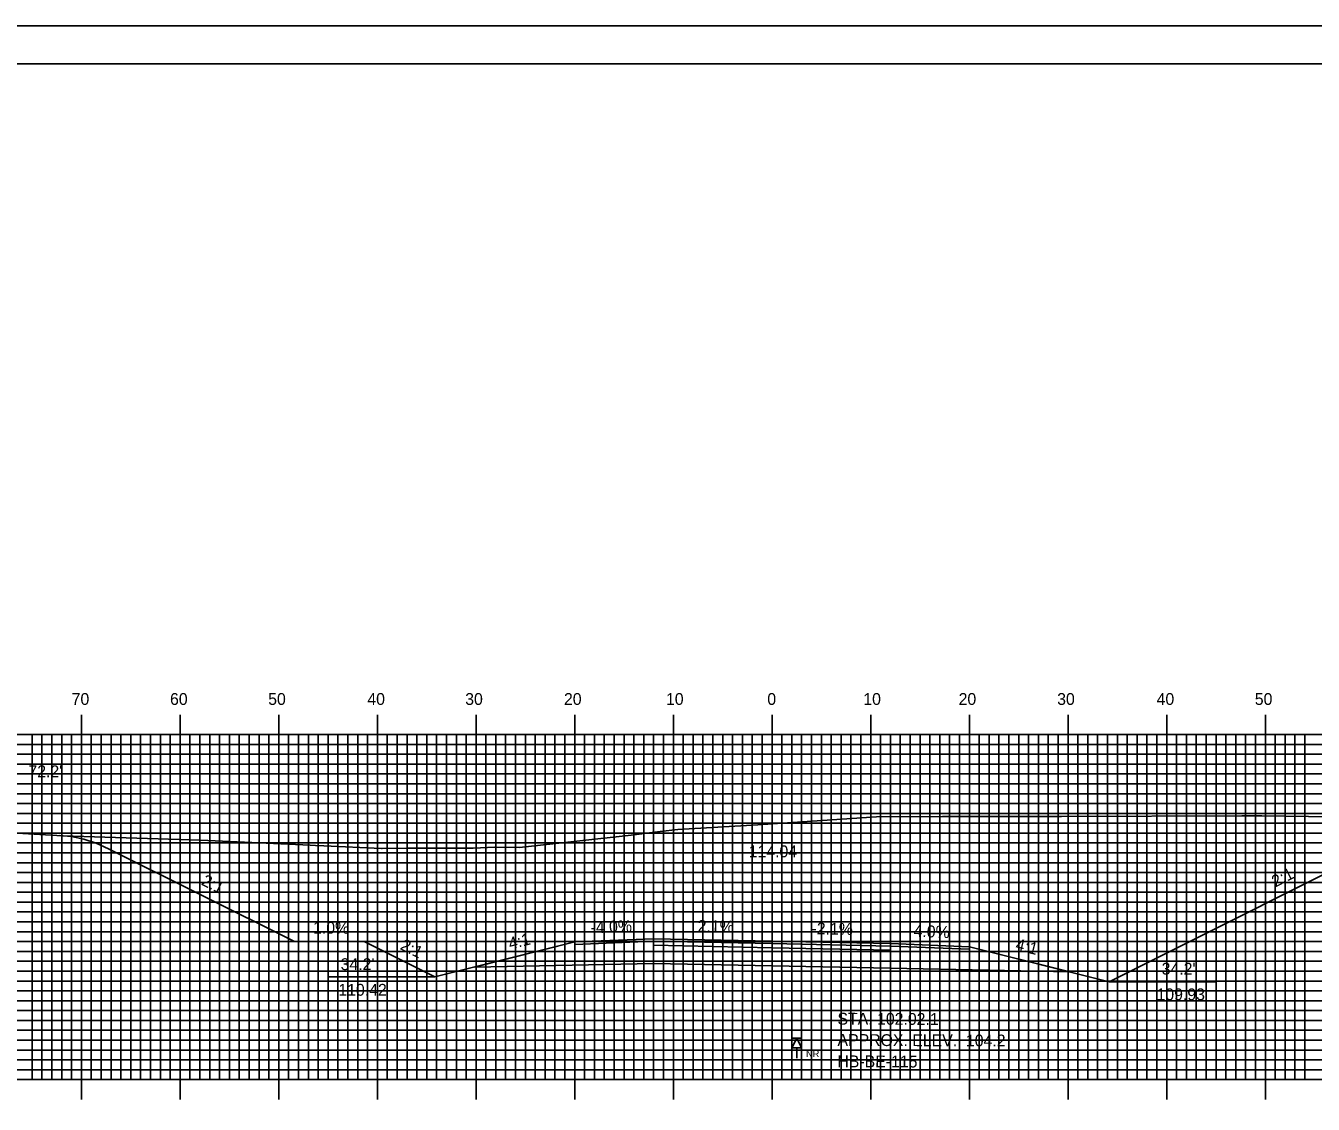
# Model space of a CAD drawing. Extents: x 1766907 to 1767250, y 442591 to 442811.
# Drawn here: x 1766996.8 to 1767127.3, y 442701.2 to 442810.5 of the extents above; entities that cross this region are included whole.
import ezdxf

# ---------------------------------------------------------------- set-up
doc = ezdxf.new("R2010")
doc.units = 0
for name, color, linetype in [('ANNOTATION', 7, 'Continuous'), ('BORDER', 7, 'Continuous'), ('BORING - NO REFUSAL', 7, 'Continuous'), ('D_Roadway_Centerline', 7, 'Continuous'), ('D_Roadway_Centerline_Text', 7, 'Continuous'), ('D_Roadway_Edge_Shoulder', 7, 'Continuous'), ('D_Roadway_Edge_TW', 7, 'Continuous'), ('D_Roadway_Pavement', 7, 'Continuous'), ('D_Roadway_SlopeLines', 7, 'Continuous'), ('D_Roadway_SubGrade', 7, 'Continuous'), ('D_Text_Standard', 7, 'Continuous'), ('H_V ANNOTATION', 7, 'Continuous'), ('MAJOR', 7, 'Continuous'), ('MINOR', 7, 'Continuous'), ('PDRAIN', 7, 'Continuous'), ('PLOT BOUNDARY', 7, 'Continuous'), ('S_Roadway_Centerline', 7, 'Continuous')]:
    doc.layers.add(name, color=color, linetype=linetype)

msp = doc.modelspace()

# ---------------------------------------------------------------- linework, layer by layer
at = {"layer": 'BORDER'}
msp.add_lwpolyline([(1766922.82, 442596.67), (1767242.82, 442596.67), (1767242.82, 442806.67), (1766922.82, 442806.67)], close=True, dxfattribs=at)
at = {"layer": 'BORING - NO REFUSAL'}
for p, q in [((1767075.4, 442707.87), (1767074.44, 442707.87)), ((1767074.92, 442706.91), (1767074.92, 442705.85))]:
    msp.add_line(p, q, dxfattribs=at)
msp.add_lwpolyline([(1767074.92, 442707.87), (1767075.4, 442706.91), (1767074.44, 442706.91)], close=True, dxfattribs=at)
at = {"layer": 'D_Roadway_Edge_Shoulder'}
for points in [[(1767060.42, 442717.95), (1767052.42, 442717.63), (1767052.42, 442717.38), (1767060.42, 442717.7)], [(1767084.42, 442717.46), (1767092.42, 442717.14), (1767092.42, 442716.89), (1767084.42, 442717.21)]]:
    msp.add_lwpolyline(points, close=True, dxfattribs=at)
at = {"layer": 'D_Roadway_Edge_TW'}
msp.add_lwpolyline([(1767060.42, 442717.7), (1767060.42, 442717.95), (1767072.42, 442717.71), (1767084.42, 442717.46), (1767084.42, 442717.21), (1767072.42, 442717.46)], close=True, dxfattribs=at)
at = {"layer": 'D_Roadway_Pavement'}
msp.add_lwpolyline([(1767060.42, 442717.29), (1767060.42, 442717.7), (1767072.42, 442717.46), (1767084.42, 442717.21), (1767084.42, 442716.79), (1767072.42, 442717.04)], close=True, dxfattribs=at)
at = {"layer": 'D_Roadway_SlopeLines'}
for points in [[(1767106.6, 442713.59), (1767137.58, 442729.09)], [(1767031.16, 442717.63), (1767023.95, 442717.71), (1767005.17, 442727.09), (1767003.92, 442727.65), (1767002.67, 442728.05), (1767001.42, 442728.31), (1767000.17, 442728.43)], [(1767038.25, 442714.09), (1767031.16, 442717.63)], [(1767052.42, 442717.63), (1767038.25, 442714.09)], [(1767092.42, 442717.14), (1767106.6, 442713.59)]]:
    msp.add_lwpolyline(points, dxfattribs=at)
at = {"layer": 'D_Roadway_SubGrade'}
msp.add_lwpolyline([(1767060.42, 442715.45), (1767042.25, 442715.09), (1767052.42, 442717.63), (1767052.42, 442717.38), (1767060.42, 442717.7), (1767072.42, 442717.46), (1767084.42, 442717.21), (1767092.42, 442716.89), (1767092.42, 442717.14), (1767102.6, 442714.59), (1767084.42, 442714.96), (1767072.42, 442715.21)], close=True, dxfattribs=at)
at = {"layer": 'MAJOR'}
for p, q in [((1767002.42, 442740.67), (1767002.42, 442738.67)), ((1767012.42, 442740.67), (1767012.42, 442738.67)), ((1767022.42, 442740.67), (1767022.42, 442738.67)), ((1767032.42, 442740.67), (1767032.42, 442738.67)), ((1767042.42, 442740.67), (1767042.42, 442738.67)), ((1767052.42, 442740.67), (1767052.42, 442738.67)), ((1767062.42, 442740.67), (1767062.42, 442738.67)), ((1767072.42, 442740.67), (1767072.42, 442738.67)), ((1767082.42, 442740.67), (1767082.42, 442738.67)), ((1767092.42, 442740.67), (1767092.42, 442738.67)), ((1767102.42, 442740.67), (1767102.42, 442738.67)), ((1767112.42, 442740.67), (1767112.42, 442738.67)), ((1767122.42, 442740.67), (1767122.42, 442738.67)), ((1766932.42, 442738.67), (1767212.42, 442738.67)), ((1766932.42, 442738.67), (1767212.42, 442738.67)), ((1767002.42, 442703.67), (1767002.42, 442738.67)), ((1767012.42, 442703.67), (1767012.42, 442738.67)), ((1767022.42, 442703.67), (1767022.42, 442738.67)), ((1767032.42, 442703.67), (1767032.42, 442738.67)), ((1767042.42, 442703.67), (1767042.42, 442738.67)), ((1767052.42, 442703.67), (1767052.42, 442738.67)), ((1767062.42, 442703.67), (1767062.42, 442738.67)), ((1767072.42, 442703.67), (1767072.42, 442738.67)), ((1767082.42, 442703.67), (1767082.42, 442738.67)), ((1767092.42, 442703.67), (1767092.42, 442738.67)), ((1767102.42, 442703.67), (1767102.42, 442738.67)), ((1767112.42, 442703.67), (1767112.42, 442738.67)), ((1767122.42, 442703.67), (1767122.42, 442738.67)), ((1766932.42, 442733.67), (1767212.42, 442733.67)), ((1766932.42, 442728.67), (1767212.42, 442728.67)), ((1766932.42, 442723.67), (1767212.42, 442723.67)), ((1766932.42, 442718.67), (1767212.42, 442718.67)), ((1766932.42, 442713.67), (1767212.42, 442713.67)), ((1766932.42, 442708.67), (1767212.42, 442708.67)), ((1766932.42, 442703.67), (1767212.42, 442703.67)), ((1766932.42, 442703.67), (1767212.42, 442703.67)), ((1767002.42, 442701.66), (1767002.42, 442703.67)), ((1767012.42, 442701.66), (1767012.42, 442703.67)), ((1767022.42, 442701.66), (1767022.42, 442703.67)), ((1767032.42, 442701.66), (1767032.42, 442703.67)), ((1767042.42, 442701.66), (1767042.42, 442703.67)), ((1767052.42, 442701.66), (1767052.42, 442703.67)), ((1767062.42, 442701.66), (1767062.42, 442703.67)), ((1767072.42, 442701.66), (1767072.42, 442703.67)), ((1767082.42, 442701.66), (1767082.42, 442703.67)), ((1767092.42, 442701.66), (1767092.42, 442703.67)), ((1767102.42, 442701.66), (1767102.42, 442703.67)), ((1767112.42, 442701.66), (1767112.42, 442703.67)), ((1767122.42, 442701.66), (1767122.42, 442703.67))]:
    msp.add_line(p, q, dxfattribs=at)
at = {"layer": 'MINOR'}
for p, q in [((1766997.42, 442703.67), (1766997.42, 442738.67)), ((1766998.42, 442703.67), (1766998.42, 442738.67)), ((1766999.42, 442703.67), (1766999.42, 442738.67)), ((1767000.42, 442703.67), (1767000.42, 442738.67)), ((1767001.42, 442703.67), (1767001.42, 442738.67)), ((1767003.42, 442703.67), (1767003.42, 442738.67)), ((1767004.42, 442703.67), (1767004.42, 442738.67)), ((1767005.42, 442703.67), (1767005.42, 442738.67)), ((1767006.42, 442703.67), (1767006.42, 442738.67)), ((1767007.42, 442703.67), (1767007.42, 442738.67)), ((1767008.42, 442703.67), (1767008.42, 442738.67)), ((1767009.42, 442703.67), (1767009.42, 442738.67)), ((1767010.42, 442703.67), (1767010.42, 442738.67)), ((1767011.42, 442703.67), (1767011.42, 442738.67)), ((1767013.42, 442703.67), (1767013.42, 442738.67)), ((1767014.42, 442703.67), (1767014.42, 442738.67)), ((1767015.42, 442703.67), (1767015.42, 442738.67)), ((1767016.42, 442703.67), (1767016.42, 442738.67)), ((1767017.42, 442703.67), (1767017.42, 442738.67)), ((1767018.42, 442703.67), (1767018.42, 442738.67)), ((1767019.42, 442703.67), (1767019.42, 442738.67)), ((1767020.42, 442703.67), (1767020.42, 442738.67)), ((1767021.42, 442703.67), (1767021.42, 442738.67)), ((1767023.42, 442703.67), (1767023.42, 442738.67)), ((1767024.42, 442703.67), (1767024.42, 442738.67)), ((1767025.42, 442703.67), (1767025.42, 442738.67)), ((1767026.42, 442703.67), (1767026.42, 442738.67)), ((1767027.42, 442703.67), (1767027.42, 442738.67)), ((1767028.42, 442703.67), (1767028.42, 442738.67)), ((1767029.42, 442703.67), (1767029.42, 442738.67)), ((1767030.42, 442703.67), (1767030.42, 442738.67)), ((1767031.42, 442703.67), (1767031.42, 442738.67)), ((1767033.42, 442703.67), (1767033.42, 442738.67)), ((1767034.42, 442703.67), (1767034.42, 442738.67)), ((1767035.42, 442703.67), (1767035.42, 442738.67)), ((1767036.42, 442703.67), (1767036.42, 442738.67)), ((1767037.42, 442703.67), (1767037.42, 442738.67)), ((1767038.42, 442703.67), (1767038.42, 442738.67)), ((1767039.42, 442703.67), (1767039.42, 442738.67)), ((1767040.42, 442703.67), (1767040.42, 442738.67)), ((1767041.42, 442703.67), (1767041.42, 442738.67)), ((1767043.42, 442703.67), (1767043.42, 442738.67)), ((1767044.42, 442703.67), (1767044.42, 442738.67)), ((1767045.42, 442703.67), (1767045.42, 442738.67)), ((1767046.42, 442703.67), (1767046.42, 442738.67)), ((1767047.42, 442703.67), (1767047.42, 442738.67)), ((1767048.42, 442703.67), (1767048.42, 442738.67)), ((1767049.42, 442703.67), (1767049.42, 442738.67)), ((1767050.42, 442703.67), (1767050.42, 442738.67)), ((1767051.42, 442703.67), (1767051.42, 442738.67)), ((1767053.42, 442703.67), (1767053.42, 442738.67)), ((1767054.42, 442703.67), (1767054.42, 442738.67)), ((1767055.42, 442703.67), (1767055.42, 442738.67)), ((1767056.42, 442703.67), (1767056.42, 442738.67)), ((1767057.42, 442703.67), (1767057.42, 442738.67)), ((1767058.42, 442703.67), (1767058.42, 442738.67)), ((1767059.42, 442703.67), (1767059.42, 442738.67)), ((1767060.42, 442703.67), (1767060.42, 442738.67)), ((1767061.42, 442703.67), (1767061.42, 442738.67)), ((1767063.42, 442703.67), (1767063.42, 442738.67)), ((1767064.42, 442703.67), (1767064.42, 442738.67)), ((1767065.42, 442703.67), (1767065.42, 442738.67)), ((1767066.42, 442703.67), (1767066.42, 442738.67)), ((1767067.42, 442703.67), (1767067.42, 442738.67)), ((1767068.42, 442703.67), (1767068.42, 442738.67)), ((1767069.42, 442703.67), (1767069.42, 442738.67)), ((1767070.42, 442703.67), (1767070.42, 442738.67)), ((1767071.42, 442703.67), (1767071.42, 442738.67)), ((1767073.42, 442703.67), (1767073.42, 442738.67)), ((1767074.42, 442703.67), (1767074.42, 442738.67)), ((1767075.42, 442703.67), (1767075.42, 442738.67)), ((1767076.42, 442703.67), (1767076.42, 442738.67)), ((1767077.42, 442703.67), (1767077.42, 442738.67)), ((1767078.42, 442703.67), (1767078.42, 442738.67)), ((1767079.42, 442703.67), (1767079.42, 442738.67)), ((1767080.42, 442703.67), (1767080.42, 442738.67)), ((1767081.42, 442703.67), (1767081.42, 442738.67)), ((1767083.42, 442703.67), (1767083.42, 442738.67)), ((1767084.42, 442703.67), (1767084.42, 442738.67)), ((1767085.42, 442703.67), (1767085.42, 442738.67)), ((1767086.42, 442703.67), (1767086.42, 442738.67)), ((1767087.42, 442703.67), (1767087.42, 442738.67)), ((1767088.42, 442703.67), (1767088.42, 442738.67)), ((1767089.42, 442703.67), (1767089.42, 442738.67)), ((1767090.42, 442703.67), (1767090.42, 442738.67)), ((1767091.42, 442703.67), (1767091.42, 442738.67)), ((1767093.42, 442703.67), (1767093.42, 442738.67)), ((1767094.42, 442703.67), (1767094.42, 442738.67)), ((1767095.42, 442703.67), (1767095.42, 442738.67)), ((1767096.42, 442703.67), (1767096.42, 442738.67)), ((1767097.42, 442703.67), (1767097.42, 442738.67)), ((1767098.42, 442703.67), (1767098.42, 442738.67)), ((1767099.42, 442703.67), (1767099.42, 442738.67)), ((1767100.42, 442703.67), (1767100.42, 442738.67)), ((1767101.42, 442703.67), (1767101.42, 442738.67)), ((1767103.42, 442703.67), (1767103.42, 442738.67)), ((1767104.42, 442703.67), (1767104.42, 442738.67)), ((1767105.42, 442703.67), (1767105.42, 442738.67)), ((1767106.42, 442703.67), (1767106.42, 442738.67)), ((1767107.42, 442703.67), (1767107.42, 442738.67)), ((1767108.42, 442703.67), (1767108.42, 442738.67)), ((1767109.42, 442703.67), (1767109.42, 442738.67)), ((1767110.42, 442703.67), (1767110.42, 442738.67)), ((1767111.42, 442703.67), (1767111.42, 442738.67)), ((1767113.42, 442703.67), (1767113.42, 442738.67)), ((1767114.42, 442703.67), (1767114.42, 442738.67)), ((1767115.42, 442703.67), (1767115.42, 442738.67)), ((1767116.42, 442703.67), (1767116.42, 442738.67)), ((1767117.42, 442703.67), (1767117.42, 442738.67)), ((1767118.42, 442703.67), (1767118.42, 442738.67)), ((1767119.42, 442703.67), (1767119.42, 442738.67)), ((1767120.42, 442703.67), (1767120.42, 442738.67)), ((1767121.42, 442703.67), (1767121.42, 442738.67)), ((1767123.42, 442703.67), (1767123.42, 442738.67)), ((1767124.42, 442703.67), (1767124.42, 442738.67)), ((1767125.42, 442703.67), (1767125.42, 442738.67)), ((1767126.42, 442703.67), (1767126.42, 442738.67)), ((1766932.42, 442737.67), (1767212.42, 442737.67)), ((1766932.42, 442736.67), (1767212.42, 442736.67)), ((1766932.42, 442735.67), (1767212.42, 442735.67)), ((1766932.42, 442734.67), (1767212.42, 442734.67)), ((1766932.42, 442732.67), (1767212.42, 442732.67)), ((1766932.42, 442731.67), (1767212.42, 442731.67)), ((1766932.42, 442730.67), (1767212.42, 442730.67)), ((1766932.42, 442729.67), (1767212.42, 442729.67)), ((1766932.42, 442727.67), (1767212.42, 442727.67)), ((1766932.42, 442726.67), (1767212.42, 442726.67)), ((1766932.42, 442725.67), (1767212.42, 442725.67)), ((1766932.42, 442724.67), (1767212.42, 442724.67)), ((1766932.42, 442722.67), (1767212.42, 442722.67)), ((1766932.42, 442721.67), (1767212.42, 442721.67)), ((1766932.42, 442720.67), (1767212.42, 442720.67)), ((1766932.42, 442719.67), (1767212.42, 442719.67)), ((1766932.42, 442717.67), (1767212.42, 442717.67)), ((1766932.42, 442716.67), (1767212.42, 442716.67)), ((1766932.42, 442715.67), (1767212.42, 442715.67)), ((1766932.42, 442714.67), (1767212.42, 442714.67)), ((1766932.42, 442712.67), (1767212.42, 442712.67)), ((1766932.42, 442711.67), (1767212.42, 442711.67)), ((1766932.42, 442710.67), (1767212.42, 442710.67)), ((1766932.42, 442709.67), (1767212.42, 442709.67)), ((1766932.42, 442707.67), (1767212.42, 442707.67)), ((1766932.42, 442706.67), (1767212.42, 442706.67)), ((1766932.42, 442705.67), (1767212.42, 442705.67)), ((1766932.42, 442704.67), (1767212.42, 442704.67))]:
    msp.add_line(p, q, dxfattribs=at)
at = {"layer": 'PDRAIN'}
for p, q in [((1767027.53, 442714.09), (1767038.25, 442714.09)), ((1767106.6, 442713.59), (1767117.37, 442713.59))]:
    msp.add_line(p, q, dxfattribs=at)
at = {"layer": 'PLOT BOUNDARY'}
msp.add_lwpolyline([(1766906.64, 442590.55), (1767246.64, 442590.55), (1767246.64, 442810.55), (1766906.64, 442810.55)], close=True, dxfattribs=at)
at = {"layer": 'S_Roadway_Centerline'}
msp.add_lwpolyline([(1766991.24, 442728.92), (1767000.5, 442728.41), (1767014.5, 442727.96), (1767025.6, 442727.45), (1767026.15, 442727.42), (1767026.99, 442727.38), (1767032.82, 442727.1), (1767032.91, 442727.1), (1767035.44, 442727.13), (1767042.13, 442727.13), (1767044.33, 442727.23), (1767046.82, 442727.21), (1767058.15, 442728.45), (1767061.07, 442728.83), (1767062.86, 442729.05), (1767070.99, 442729.51), (1767082.99, 442730.32), (1767089.69, 442730.35), (1767101.75, 442730.34), (1767120.05, 442730.41), (1767121.22, 442730.41), (1767122.07, 442730.41), (1767133.86, 442730.25)], dxfattribs=at)

# ---------------------------------------------------------------- texts
at = {"layer": 'ANNOTATION'}
for s, rotation, p in [('2:1', 333.4346, (1767014.5, 442723.47)), ('2:1', 26.9724, (1767123.44, 442723.15)), ('1.0%', 359.4283, (1767025.89, 442718.49)), ('-4.0%', 2.2905, (1767054.05, 442718.5)), ('2.1%', 358.8209, (1767064.87, 442718.66)), ('-2.1%', 358.816, (1767076.41, 442718.42)), ('-4.0%', 357.7095, (1767086.21, 442718.19)), ('2:1', 333.4399, (1767034.64, 442716.93)), ('4:1', 14.035, (1767045.87, 442716.86)), ('4:1', 345.9616, (1767097.02, 442716.85))]:
    msp.add_text(s, height=1.2, rotation=rotation, dxfattribs=at).set_placement(p)
for s, p in [("34.2'", (1767028.69, 442714.78)), ("34.2'", (1767111.91, 442714.32)), ('110.42', (1767028.46, 442712.18)), ('109.93', (1767111.39, 442711.72))]:
    msp.add_text(s, height=1.2, dxfattribs=at).set_placement(p)
at = {"layer": 'BORING - NO REFUSAL'}
for s, p in [('STA. 102.02.1', (1767079.05, 442709.25)), ('APPROX. ELEV.  104.2', (1767079.05, 442707.09)), ('HB-BE-115', (1767079.04, 442704.93))]:
    msp.add_text(s, height=1.2, rotation=359.8142, dxfattribs=at).set_placement(p)
msp.add_text('NR', height=0.7, dxfattribs=at).set_placement((1767075.86, 442705.95))
at = {"layer": 'D_Roadway_Centerline'}
for s, p in [('C', (1767072.42, 442717.71)), ('L', (1767072.42, 442717.7))]:
    msp.add_text(s, height=0.0146, dxfattribs=at).set_placement(p)
at = {"layer": 'D_Roadway_Centerline_Text'}
msp.add_text('114.04', height=1.2, dxfattribs=at).set_placement((1767070.05, 442726.22))
at = {"layer": 'D_Text_Standard'}
msp.add_text("72.2'", height=1.2, dxfattribs=at).set_placement((1766997.05, 442734.34))
at = {"layer": 'H_V ANNOTATION'}
for s, p in [('70', (1767001.43, 442741.67)), ('60', (1767011.4, 442741.67)), ('50', (1767021.35, 442741.67)), ('40', (1767031.4, 442741.67)), ('30', (1767041.32, 442741.67)), ('20', (1767051.33, 442741.67)), ('10', (1767061.67, 442741.67)), ('0', (1767071.94, 442741.67)), ('10', (1767081.67, 442741.67)), ('20', (1767091.33, 442741.67)), ('30', (1767101.32, 442741.67)), ('40', (1767111.4, 442741.67)), ('50', (1767121.35, 442741.67))]:
    msp.add_text(s, height=1.2, dxfattribs=at).set_placement(p)

doc.saveas('drawing.dxf')
